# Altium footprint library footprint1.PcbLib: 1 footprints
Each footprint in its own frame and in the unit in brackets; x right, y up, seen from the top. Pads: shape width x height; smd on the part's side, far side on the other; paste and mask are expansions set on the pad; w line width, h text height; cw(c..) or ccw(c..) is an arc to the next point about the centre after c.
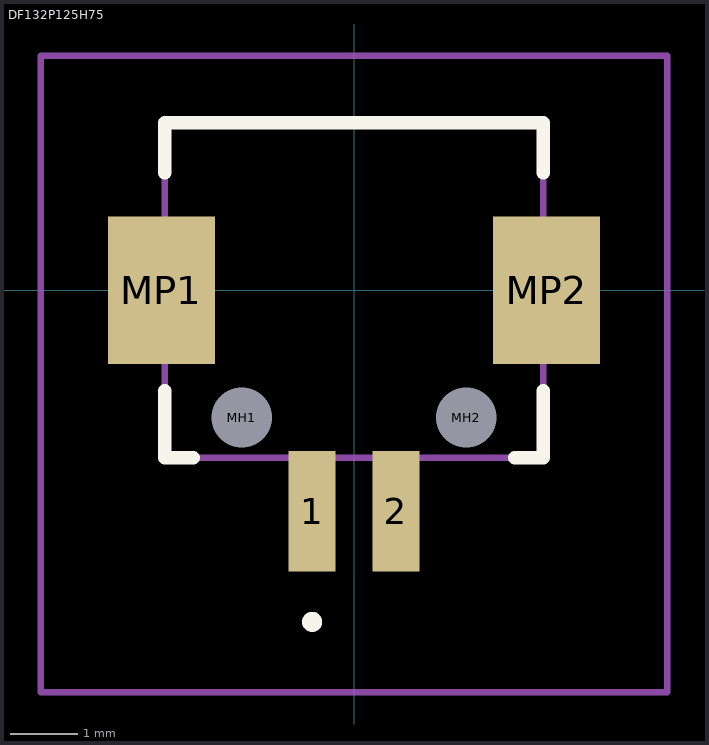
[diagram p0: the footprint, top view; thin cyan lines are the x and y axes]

## DF132P125H75 [mm]
pads (6):
  rect 0.7x1.8 smd: 1(-0.625,-3.3) 2(0.625,-3.3)
  round 0.45 hole 0.9 unplated: MH1(-1.675,-1.9) MH2(1.675,-1.9)
  rect 1.6x2.2 smd: MP1(-2.875,0) MP2(2.875,0)
Top Overlay:
  lines w0.2: -2.825,-1.5 -2.825,-2.5 -2.4,-2.5 ; -2.825,1.75 -2.825,2.5 2.825,2.5 2.825,1.75 ; 2.4,-2.5 2.825,-2.5 2.825,-1.5 ; -0.625,-5 ccw(c-0.625,-4.95) -0.625,-4.9 ; -0.625,-5 cw(c-0.625,-4.95) -0.625,-4.9 ; -0.625,-5 ccw(c-0.625,-4.95) -0.625,-4.9
Mechanical 13:
  lines w0.1: -2.825,-2.5 2.825,-2.5 2.825,2.5 -2.825,2.5 -2.825,-2.5
Mechanical 15:
  lines w0.1: -4.675,-6 4.675,-6 4.675,3.5 -4.675,3.5 -4.675,-6
3D body "DF13-2P-1.25H_75_.stp": height 3.85, standoff -1.7, extent -3.515,-4.13 3.515,2.5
